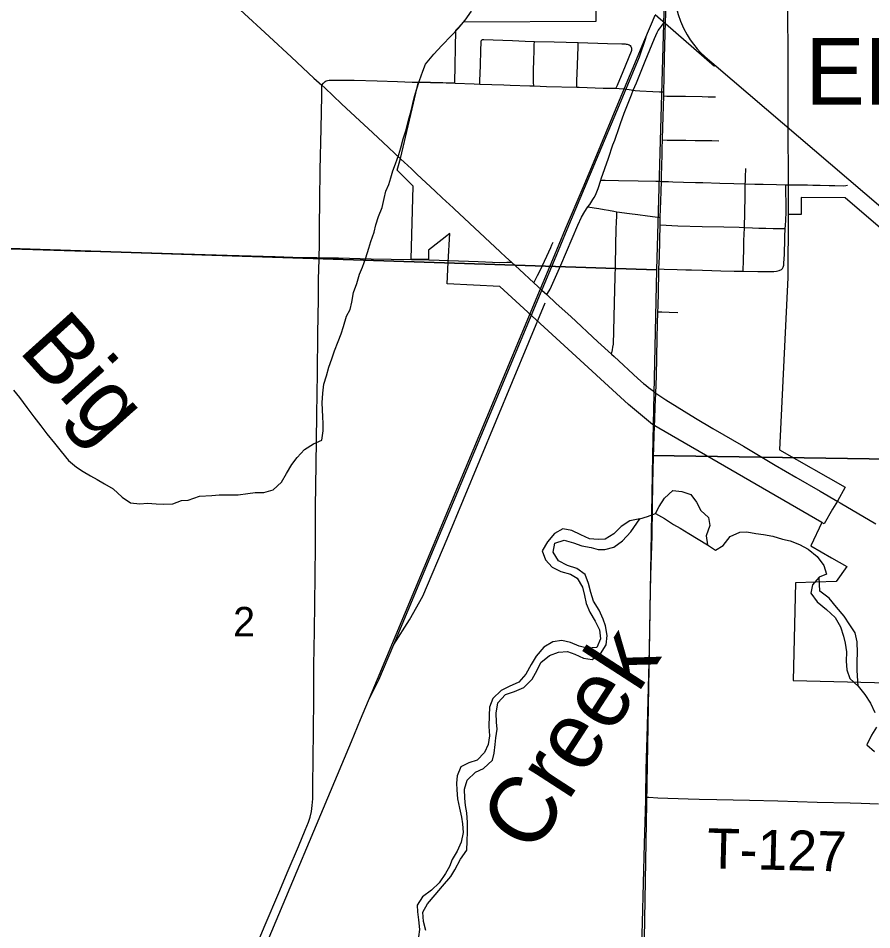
# Model space of a CAD drawing. Extents: x 0 to 34, y 0 to 22.
# Drawn here: x 7.066 to 8.28, y 14.663 to 15.96 of the extents above; entities that cross this region are included whole.
import ezdxf

# ---------------------------------------------------------------- set-up
doc = ezdxf.new("R2010")
doc.units = 0
for name, color, linetype in [('Default', 7, 'Continuous'), ('GM_X_City_Street', 7, 'Continuous'), ('GM_X_Corporation', 7, 'Continuous'), ('GM_X_County_Road', 7, 'Continuous'), ('GM_X_County_Road_Text', 7, 'Continuous'), ('GM_X_Interchange_Ramps', 7, 'Continuous'), ('GM_X_Major_River_Text', 7, 'Continuous'), ('GM_X_Minor_River', 7, 'Continuous'), ('GM_X_Section', 7, 'Continuous'), ('GM_X_Section_Text', 7, 'Continuous'), ('GM_X_State_Shield', 7, 'Continuous'), ('GM_X_Unincorporated', 7, 'Continuous'), ('GM_X_Unincorporated_Location', 7, 'Continuous'), ('GM_X_US_Location', 7, 'Continuous'), ('GM_X_US_Shield', 7, 'Continuous')]:
    doc.layers.add(name, color=color, linetype=linetype)

msp = doc.modelspace()

# ---------------------------------------------------------------- linework, layer by layer
at = {"layer": 'Default'}
for points in [[(8.8, 15.3246), (8.8, 16.334), (7.9948, 16.3527), (7.9737, 15.6015), (7.9679, 15.3374)], [(8.8, 14.3281), (8.8, 15.3246), (7.9679, 15.3374), (7.9551, 14.5952), (7.9448, 14.3373)]]:
    msp.add_lwpolyline(points, close=True, dxfattribs=at)
msp.add_lwpolyline([(8.385, 15.5812), (8.2421, 15.7041), (8.1796, 15.7048), (8.1793, 15.6802), (8.1608, 15.6804), (8.1604, 15.591), (8.1484, 15.3458), (8.2418, 15.2923), (8.2312, 15.2728), (8.2242, 15.2612), (8.2123, 15.2402), (8.2087, 15.2423), (8.1932, 15.209), (8.2227, 15.1919), (8.2443, 15.1795), (8.2293, 15.1583), (8.1715, 15.1566), (8.1681, 15.0172), (8.4377, 15.0106)], dxfattribs=at)
at = {"layer": 'GM_X_City_Street'}
for p, q in [((7.9839, 15.8491), (7.984, 15.8548)), ((7.9788, 15.6656), (7.9791, 15.676)), ((7.6251, 15.6163), (7.6499, 15.6157))]:
    msp.add_line(p, q, dxfattribs=at)
for points in [[(7.9867, 15.9546), (7.9871, 15.9656), (7.9887, 16.009), (7.989, 16.0249)], [(7.984, 15.8548), (7.9845, 15.8758), (7.9852, 15.9036), (7.9861, 15.9377), (7.9867, 15.9546)], [(7.9822, 15.7866), (7.9828, 15.8046), (7.9839, 15.8491)], [(7.9807, 15.7276), (7.981, 15.7391), (7.9811, 15.7457), (7.9814, 15.7534), (7.9816, 15.7618), (7.9819, 15.7745), (7.9822, 15.7866)], [(7.9791, 15.676), (7.9795, 15.6885), (7.9798, 15.6992), (7.9802, 15.7135), (7.9807, 15.7276)], [(7.9772, 15.6029), (7.9778, 15.6206), (7.9788, 15.6656)], [(6.9928, 15.6334), (7.0402, 15.6319), (7.0868, 15.6305), (7.1613, 15.6285), (7.2265, 15.6267), (7.2855, 15.625), (7.3632, 15.6225), (7.4315, 15.6206), (7.4563, 15.6198), (7.4905, 15.6191), (7.4938, 15.619)], [(7.4938, 15.619), (7.5215, 15.6186), (7.5681, 15.6174), (7.5961, 15.6171), (7.6251, 15.6163)], [(7.6499, 15.6157), (7.6645, 15.6153), (7.6784, 15.6149)], [(7.6784, 15.6149), (7.7201, 15.6135), (7.7511, 15.6123), (7.7608, 15.6124), (7.7675, 15.6124)], [(7.9757, 15.5421), (7.9759, 15.5494), (7.9764, 15.5698), (7.9767, 15.58), (7.9769, 15.589), (7.9772, 15.6029)], [(7.9727, 15.4263), (7.9735, 15.4504), (7.9748, 15.5046), (7.9753, 15.5244), (7.9757, 15.5421)], [(7.9709, 15.3803), (7.9712, 15.3885), (7.9719, 15.4071), (7.9727, 15.4256), (7.9727, 15.4263)], [(7.9584, 14.8515), (7.9592, 14.8907), (7.9611, 14.9529), (7.9614, 14.9715), (7.9631, 15.043), (7.964, 15.0834), (7.9648, 15.1207), (7.9658, 15.1673), (7.9674, 15.2232), (7.9681, 15.2636), (7.9685, 15.2978), (7.9696, 15.3351), (7.9709, 15.3803)], [(7.9516, 14.5947), (7.952, 14.6079), (7.9537, 14.6731), (7.9564, 14.785), (7.9583, 14.8472), (7.9584, 14.8515)]]:
    msp.add_lwpolyline(points, dxfattribs=at)
at = {"layer": 'GM_X_Corporation'}
msp.add_line((7.9718, 15.9648), (8.0563, 15.8914), dxfattribs=at)
for points in [[(8.0101, 16.0566), (8.0064, 16.0438), (8.0032, 16.0324), (8.0011, 16.0214), (8, 16.0122), (7.9995, 15.9972), (8, 15.9869), (8.0018, 15.9759), (8.0044, 15.965), (8.008, 15.9554), (8.0122, 15.9455), (8.0171, 15.9362), (8.0217, 15.929), (8.0261, 15.9226), (8.0314, 15.9163), (8.0364, 15.9108), (8.0427, 15.9049), (8.0587, 15.8914), (8.5043, 15.5105), (8.8, 15.2581)], [(7.1503, 14), (7.403, 14.6041), (7.5398, 14.9308), (7.5529, 14.9621), (7.5767, 15.0193), (7.6567, 15.2102), (7.6827, 15.2726), (7.7324, 15.3914), (7.8087, 15.5745), (7.8264, 15.6162), (7.8444, 15.66), (7.8693, 15.7188), (7.8863, 15.7598), (7.9189, 15.8374), (7.9573, 15.9292), (7.972, 15.9642)], [(7.6, 15.0687), (7.6589, 15.2093), (7.6849, 15.2717), (7.7346, 15.3905), (7.8109, 15.5736), (7.8286, 15.6153), (7.8466, 15.6591), (7.8715, 15.7179), (7.8885, 15.7589), (7.9211, 15.8365), (7.9496, 15.9048), (7.9588, 15.9329)], [(7.6, 15.0687), (7.6223, 15.1039), (7.6414, 15.1375), (7.6758, 15.2191), (7.8155, 15.5548)], [(7.5633, 14.9872), (7.5789, 15.0184), (7.6, 15.0687)]]:
    msp.add_lwpolyline(points, dxfattribs=at)
at = {"layer": 'GM_X_County_Road'}
for points in [[(7.0027, 16.3195), (7.0291, 16.2956), (7.0799, 16.2498), (7.1558, 16.1809), (7.1925, 16.1473), (7.2336, 16.1094), (7.2657, 16.08), (7.3452, 16.0057), (7.3814, 15.9718), (7.4226, 15.9339), (7.4544, 15.9041), (7.4861, 15.8744), (7.4979, 15.8643), (7.5018, 15.8606), (7.5256, 15.8381), (7.5518, 15.8138)], [(7.5518, 15.8138), (7.5634, 15.803), (7.5845, 15.7833), (7.6096, 15.7598)], [(7.6096, 15.7598), (7.6154, 15.7544), (7.6194, 15.7507), (7.6255, 15.745), (7.6316, 15.7394), (7.633, 15.738)], [(7.633, 15.738), (7.6588, 15.7137), (7.669, 15.7043)], [(7.669, 15.7043), (7.6846, 15.6899), (7.686, 15.6886)], [(7.686, 15.6886), (7.7514, 15.6273), (7.7595, 15.6198)], [(7.7595, 15.6198), (7.7675, 15.6124), (7.7787, 15.6021), (7.7992, 15.5832), (7.8107, 15.5728), (7.8177, 15.5664), (7.8311, 15.5539), (7.8517, 15.5351), (7.8904, 15.4994), (7.9099, 15.4817), (7.9133, 15.4786), (7.9473, 15.4471), (7.9554, 15.4401), (7.9585, 15.4374), (7.9621, 15.4345), (7.9687, 15.4294), (7.9727, 15.4263), (7.9871, 15.4167), (8.0293, 15.3908), (8.054, 15.376), (8.0972, 15.3507), (8.1423, 15.324), (8.1717, 15.3068), (8.2064, 15.2867), (8.2315, 15.2723)], [(8.2315, 15.2723), (8.2349, 15.2701), (8.2857, 15.2401)]]:
    msp.add_lwpolyline(points, dxfattribs=at)
at = {"layer": 'GM_X_Interchange_Ramps'}
for points in [[(7.4938, 15.619), (7.4942, 15.6382), (7.4944, 15.6631), (7.4948, 15.7004), (7.4953, 15.7439), (7.4967, 15.8029), (7.4975, 15.8495), (7.4979, 15.8643)], [(7.4979, 15.8643), (7.5002, 15.8673), (7.5025, 15.8695), (7.5041, 15.8706), (7.5058, 15.8713), (7.5081, 15.8716), (7.511, 15.8718), (7.5174, 15.8718), (7.5436, 15.8714), (7.5766, 15.8704), (7.6053, 15.8695), (7.626, 15.8689), (7.6354, 15.8685), (7.6364, 15.8685)], [(7.6364, 15.8685), (7.6524, 15.8681), (7.6746, 15.8676), (7.6872, 15.8673)], [(7.6872, 15.8673), (7.7145, 15.8663), (7.7225, 15.866)], [(8.1575, 15.7228), (8.1624, 15.7228), (8.1677, 15.7227), (8.1752, 15.7227), (8.1806, 15.7227)], [(8.1806, 15.7227), (8.1884, 15.7225), (8.1959, 15.7224), (8.2066, 15.7221), (8.2191, 15.7218), (8.2273, 15.7216), (8.2393, 15.7214), (8.2428, 15.7215), (8.2455, 15.7222)], [(7.4039, 14.6382), (7.4173, 14.6697), (7.4366, 14.7155), (7.4498, 14.747), (7.4643, 14.7813), (7.4739, 14.8043), (7.4786, 14.8158), (7.4813, 14.823), (7.4831, 14.8309), (7.4842, 14.8396), (7.4849, 14.8491), (7.4851, 14.8677), (7.4858, 14.9453), (7.4862, 14.9919), (7.4864, 15.0386), (7.4873, 15.0883), (7.4881, 15.166), (7.4886, 15.2095), (7.4889, 15.2654), (7.489, 15.2934), (7.4899, 15.3586), (7.4905, 15.3959), (7.4915, 15.4549), (7.4922, 15.5108), (7.4929, 15.5605), (7.4932, 15.5885), (7.4937, 15.6165), (7.4938, 15.619)], [(7.9584, 14.8515), (7.963, 14.8512), (7.9754, 14.8506), (8.0189, 14.8492), (8.0345, 14.8488), (8.0594, 14.8482), (8.106, 14.8472), (8.1464, 14.846), (8.2024, 14.8444), (8.2491, 14.8432), (8.2646, 14.8428), (8.2895, 14.8421)]]:
    msp.add_lwpolyline(points, dxfattribs=at)
at = {"layer": 'GM_X_Section'}
for points in [[(7.3235, 15.2796), (7.3412, 15.2806), (7.3519, 15.2817), (7.3789, 15.2817), (7.3926, 15.2836), (7.4028, 15.2847), (7.415, 15.2847), (7.4287, 15.2885), (7.4405, 15.2995), (7.4473, 15.3117), (7.455, 15.3246), (7.4626, 15.3349), (7.4732, 15.3463), (7.4858, 15.3542), (7.4976, 15.3595), (7.4995, 15.3728), (7.4995, 15.3831), (7.4991, 15.3926), (7.4987, 15.4025), (7.4984, 15.4127), (7.4991, 15.426), (7.5007, 15.4389), (7.5045, 15.4511), (7.5075, 15.4633), (7.5121, 15.475), (7.5159, 15.4864), (7.5208, 15.4997), (7.525, 15.5107), (7.5285, 15.521), (7.533, 15.5358), (7.538, 15.5453), (7.5406, 15.5556), (7.5429, 15.5693), (7.5475, 15.5822), (7.5513, 15.5955), (7.5555, 15.6057), (7.5605, 15.6186), (7.5646, 15.6323), (7.5673, 15.6422), (7.5723, 15.6555), (7.5745, 15.6657), (7.5784, 15.6775), (7.5833, 15.6904), (7.5864, 15.7034), (7.5886, 15.7136), (7.5928, 15.7231), (7.5959, 15.7326), (7.5989, 15.7425), (7.6024, 15.7524), (7.6073, 15.766), (7.61, 15.7755), (7.6134, 15.7881), (7.6176, 15.801), (7.621, 15.8147), (7.6248, 15.828), (7.6271, 15.8386), (7.6294, 15.8485), (7.6324, 15.858), (7.6366, 15.8709), (7.6412, 15.8842), (7.645, 15.8945), (7.6572, 15.9085), (7.6686, 15.921), (7.6823, 15.9351), (7.6914, 15.945), (7.7017, 15.9571), (7.7108, 15.9697)], [(7.0594, 15.4307), (7.0678, 15.4201), (7.0781, 15.4057), (7.088, 15.3925), (7.0983, 15.3796), (7.1067, 15.3686), (7.1174, 15.355), (7.1269, 15.3433), (7.1375, 15.3304), (7.1486, 15.321), (7.1581, 15.3146), (7.1687, 15.3085), (7.1782, 15.3036), (7.1885, 15.2972), (7.201, 15.2901), (7.2136, 15.2784), (7.2254, 15.27), (7.2387, 15.2686), (7.25, 15.2697), (7.2622, 15.269), (7.272, 15.2683), (7.2857, 15.2687), (7.2982, 15.2733), (7.3077, 15.2741), (7.3235, 15.2796)], [(7.9723, 15.2549), (7.9852, 15.2477), (7.9977, 15.2393), (8.0072, 15.234), (8.0198, 15.2268), (8.0464, 15.2104)]]:
    msp.add_lwpolyline(points, dxfattribs=at)
at = {"layer": 'GM_X_Section_Text'}
for points in [[(7.9498, 15.2473), (7.9608, 15.2507), (7.9723, 15.2549), (7.9776, 15.2651), (7.9852, 15.2769), (7.997, 15.2876), (8.0099, 15.2864), (8.0225, 15.2819), (8.0305, 15.2712), (8.0365, 15.2594), (8.0476, 15.2495), (8.0495, 15.2378), (8.0445, 15.2233), (8.0464, 15.2104), (8.0574, 15.2028), (8.0685, 15.2096), (8.0784, 15.2222), (8.0921, 15.2283), (8.102, 15.229), (8.1149, 15.2267), (8.1259, 15.2252), (8.1389, 15.2229), (8.1529, 15.2187), (8.1636, 15.2161), (8.1769, 15.2111), (8.1894, 15.2043), (8.202, 15.194), (8.2115, 15.1811), (8.2153, 15.1689), (8.205, 15.1644)], [(7.9498, 15.2473), (7.9357, 15.2446), (7.9236, 15.2367), (7.9129, 15.226), (7.9007, 15.2184), (7.8905, 15.2181), (7.8783, 15.2188), (7.8661, 15.2245), (7.8532, 15.2306), (7.8403, 15.2333), (7.8285, 15.2264), (7.8186, 15.2147), (7.8113, 15.2021), (7.8159, 15.1892), (7.8254, 15.1786), (7.8376, 15.1725), (7.8513, 15.1687), (7.8608, 15.163), (7.8684, 15.1501), (7.8714, 15.1383), (7.8737, 15.1269), (7.879, 15.1147), (7.8866, 15.1018), (7.8927, 15.0897), (7.8942, 15.0767), (7.8889, 15.0646), (7.8752, 15.0634), (7.8638, 15.0665), (7.8516, 15.0714), (7.839, 15.0741), (7.8261, 15.0726), (7.8136, 15.065), (7.8025, 15.0521), (7.7953, 15.0403), (7.7877, 15.0262), (7.7778, 15.0152), (7.7641, 15.0088), (7.7527, 15.0031), (7.7409, 14.9917), (7.7363, 14.9795), (7.7355, 14.9674), (7.7351, 14.9518), (7.7363, 14.9389), (7.7344, 14.9263), (7.729, 14.915), (7.7184, 14.9039), (7.7066, 14.9005), (7.6952, 14.8944), (7.6902, 14.8819), (7.6891, 14.8713), (7.6898, 14.8618), (7.6906, 14.8492), (7.6936, 14.8356), (7.6963, 14.823), (7.6978, 14.8135), (7.6986, 14.801), (7.6959, 14.7873), (7.6902, 14.7748), (7.6833, 14.7626), (7.6791, 14.7527), (7.6738, 14.7429), (7.6647, 14.7296), (7.6536, 14.7193), (7.6411, 14.7094), (7.6331, 14.6977), (7.6338, 14.6882), (7.635, 14.6768), (7.6365, 14.6631), (7.6353, 14.6528)], [(7.6456, 14.6616), (7.6422, 14.6745), (7.6414, 14.6878), (7.6479, 14.6996), (7.6589, 14.7125), (7.6692, 14.7246), (7.681, 14.7387), (7.6871, 14.7482), (7.6951, 14.7634), (7.7039, 14.7759), (7.7043, 14.7888), (7.705, 14.8021), (7.705, 14.8154), (7.7039, 14.8291), (7.702, 14.8397), (7.7009, 14.85), (7.7005, 14.8629), (7.7043, 14.8754), (7.7161, 14.8868), (7.7275, 14.8922), (7.7404, 14.9043), (7.7427, 14.9138), (7.7443, 14.9263), (7.7454, 14.9358), (7.7469, 14.9484), (7.7462, 14.9583), (7.7458, 14.9708), (7.7481, 14.9856), (7.7587, 14.9974), (7.7717, 15.0016), (7.785, 15.0073), (7.7968, 15.0194), (7.804, 15.0319), (7.809, 15.043), (7.8215, 15.0528), (7.8341, 15.0578), (7.847, 15.0585), (7.8573, 15.0551), (7.8698, 15.049), (7.8824, 15.0475), (7.8942, 15.0555), (7.9022, 15.068), (7.9033, 15.0813), (7.9011, 15.095), (7.898, 15.1045), (7.8919, 15.1174), (7.8843, 15.1303), (7.8802, 15.1428), (7.8771, 15.1554), (7.8722, 15.1683), (7.8604, 15.177), (7.8471, 15.1812), (7.8341, 15.1877), (7.8265, 15.1999), (7.8292, 15.2128), (7.8422, 15.2173), (7.8558, 15.2135), (7.8676, 15.209), (7.8806, 15.2067), (7.8905, 15.2036), (7.9003, 15.2036), (7.9129, 15.207), (7.9255, 15.2162), (7.9373, 15.2287), (7.9498, 15.2473)], [(8.205, 15.1644), (8.1955, 15.1534), (8.1932, 15.1416), (8.202, 15.1294), (8.2156, 15.1184), (8.2278, 15.107), (8.2354, 15.0937), (8.2396, 15.0804), (8.2419, 15.0705), (8.2438, 15.0584), (8.2434, 15.0451), (8.2445, 15.0325), (8.2487, 15.0204), (8.2605, 15.0094)], [(8.2605, 15.0094), (8.259, 15.0318), (8.259, 15.0447), (8.2597, 15.0568), (8.259, 15.0724), (8.2563, 15.085), (8.2484, 15.0967), (8.2407, 15.1089), (8.2297, 15.1218), (8.2191, 15.1347), (8.2061, 15.1443), (8.205, 15.1644)], [(8.2605, 15.0094), (8.27, 14.9976), (8.278, 14.985), (8.284, 14.9717)], [(8.2867, 14.9508), (8.2795, 14.9394), (8.273, 14.9258), (8.2836, 14.9163)]]:
    msp.add_lwpolyline(points, dxfattribs=at)
at = {"layer": 'GM_X_Unincorporated_Location'}
for points in [[(8.0033, 16.6164), (7.9948, 16.3527), (7.9737, 15.6015), (6.9963, 15.6339), (7.0019, 16.6421)], [(6.9963, 15.6339), (7.9737, 15.6015), (7.9679, 15.3374), (7.9551, 14.5952), (6.9808, 14.6254)]]:
    msp.add_lwpolyline(points, close=True, dxfattribs=at)
at = {"layer": 'GM_X_US_Location'}
for points in [[(7.8177, 15.5664), (7.8208, 15.5718), (7.8223, 15.5744), (7.8264, 15.5828), (7.8378, 15.6082), (7.862, 15.6653), (7.8672, 15.6765), (7.8716, 15.6847), (7.875, 15.6899), (7.8762, 15.6915), (7.8788, 15.6948), (7.8831, 15.7016), (7.8849, 15.7046), (7.8868, 15.7078), (7.8889, 15.7126), (7.8905, 15.7172), (7.8945, 15.7294), (7.895, 15.7312), (7.9052, 15.7605), (7.9118, 15.7794), (7.9142, 15.7862), (7.9204, 15.8042), (7.9224, 15.81), (7.9276, 15.8248), (7.938, 15.8507), (7.9407, 15.8573), (7.9451, 15.8679), (7.9577, 15.8986), (7.9709, 15.931), (7.9746, 15.9395), (7.9761, 15.9422), (7.9778, 15.9448), (7.9808, 15.9486), (7.9832, 15.9515), (7.9867, 15.9546)], [(7.7225, 15.866), (7.7226, 15.8707), (7.7232, 15.8926), (7.7238, 15.9141), (7.7241, 15.925), (7.7241, 15.9258), (7.7242, 15.9266), (7.7244, 15.9272), (7.7246, 15.9279), (7.725, 15.9284)], [(7.725, 15.9284), (7.7258, 15.9291), (7.7264, 15.9292), (7.7271, 15.9293), (7.7281, 15.9294), (7.7416, 15.929), (7.7688, 15.9279), (7.7869, 15.9272), (7.8, 15.9267), (7.8283, 15.9259), (7.8625, 15.925), (7.9041, 15.9238), (7.9242, 15.9233), (7.9289, 15.9232), (7.9306, 15.923), (7.9321, 15.9228), (7.9333, 15.9225), (7.9346, 15.9219), (7.936, 15.9209), (7.937, 15.9197), (7.9378, 15.9184), (7.9381, 15.9169), (7.9381, 15.9153), (7.938, 15.9139), (7.9376, 15.9123), (7.926, 15.8836), (7.9176, 15.8641), (7.9158, 15.86)], [(7.799, 15.8634), (7.7989, 15.8682), (7.7988, 15.8781), (7.7989, 15.8876), (7.7991, 15.8976), (7.7997, 15.9159), (7.7999, 15.922), (7.8, 15.9267)], [(7.8604, 15.8615), (7.8604, 15.8662), (7.8605, 15.8715), (7.8608, 15.8807), (7.8622, 15.9192), (7.8625, 15.925)], [(7.7225, 15.866), (7.7564, 15.8649), (7.7655, 15.8646), (7.7934, 15.8636), (7.799, 15.8634), (7.8174, 15.8627), (7.8604, 15.8615), (7.8637, 15.8614), (7.8979, 15.8604), (7.9102, 15.8601), (7.9158, 15.86), (7.9206, 15.8599), (7.9284, 15.859), (7.935, 15.8581), (7.9407, 15.8573), (7.9432, 15.8569), (7.9501, 15.8562), (7.9686, 15.8556), (7.978, 15.8551), (7.984, 15.8548)], [(7.9839, 15.8491), (7.9884, 15.849), (8.0151, 15.8486), (8.0386, 15.8482), (8.0473, 15.848), (8.0577, 15.8479)], [(7.9822, 15.7866), (7.989, 15.7864), (8.0021, 15.7862), (8.0152, 15.786), (8.0289, 15.7858), (8.0409, 15.7856), (8.0525, 15.7855), (8.0623, 15.7853)], [(8.0969, 15.5997), (8.0971, 15.6049), (8.0972, 15.6109), (8.0975, 15.6192), (8.0977, 15.6275), (8.0979, 15.6366), (8.0981, 15.6438), (8.0983, 15.6515), (8.0986, 15.662), (8.0986, 15.6628), (8.0992, 15.6823), (8.0994, 15.6906), (8.0997, 15.6993), (8.0998, 15.7091), (8.1, 15.7197), (8.1, 15.724), (8.1001, 15.7275), (8.1003, 15.7336), (8.1006, 15.7459)], [(7.8945, 15.7294), (7.9005, 15.7293), (7.9194, 15.7288), (7.9477, 15.7285), (7.9725, 15.7278), (7.9772, 15.7277), (7.9807, 15.7276)], [(7.9807, 15.7276), (7.9909, 15.7273), (7.9971, 15.727), (8.0123, 15.7266), (8.0292, 15.7261), (8.0394, 15.7258), (8.0637, 15.7251), (8.0835, 15.7245), (8.1, 15.724), (8.1137, 15.7237), (8.1252, 15.7235), (8.1445, 15.7231), (8.1575, 15.7228)], [(8.158, 15.6803), (8.1581, 15.6883), (8.158, 15.6969), (8.1578, 15.712), (8.1575, 15.7228)], [(7.8762, 15.6915), (7.8848, 15.69), (7.8917, 15.6888), (7.8991, 15.6875), (7.9055, 15.6864), (7.913, 15.6851), (7.9173, 15.6844)], [(7.9099, 15.4817), (7.9111, 15.4881), (7.9117, 15.4915), (7.9123, 15.4959), (7.913, 15.5145), (7.914, 15.5548), (7.915, 15.5918), (7.9152, 15.6068), (7.9159, 15.6377), (7.9165, 15.6593), (7.9169, 15.6704), (7.9171, 15.6778), (7.9173, 15.6844)], [(7.9173, 15.6844), (7.9353, 15.6819), (7.9471, 15.6803), (7.9611, 15.6785), (7.9719, 15.677), (7.9791, 15.676)], [(8.1514, 15.6021), (8.1529, 15.6036), (8.154, 15.6056), (8.1548, 15.6083), (8.1549, 15.6114), (8.1555, 15.6237), (8.1562, 15.6458), (8.1564, 15.6526), (8.1565, 15.6569), (8.1567, 15.6603), (8.1572, 15.6647), (8.1576, 15.6722), (8.1578, 15.6756), (8.158, 15.6803)], [(7.9788, 15.6656), (8.0041, 15.6645), (8.0384, 15.6634), (8.0696, 15.6628), (8.0914, 15.6622), (8.0986, 15.662), (8.1104, 15.6615), (8.1194, 15.6612), (8.1292, 15.6609), (8.1394, 15.6607), (8.147, 15.6605), (8.1548, 15.6604), (8.1567, 15.6603)], [(7.7992, 15.5832), (7.8011, 15.5868), (7.8046, 15.5935), (7.8089, 15.6019), (7.8233, 15.6333), (7.8249, 15.6371), (7.8266, 15.6412)], [(7.9772, 15.6029), (7.9844, 15.6026), (8.0031, 15.602), (8.0154, 15.6017), (8.0234, 15.6015), (8.039, 15.6011), (8.0524, 15.6007), (8.0654, 15.6004), (8.0839, 15.5999), (8.0969, 15.5997), (8.118, 15.5994), (8.1367, 15.5992), (8.1405, 15.5994), (8.1443, 15.5997), (8.1483, 15.6007), (8.1514, 15.6021)], [(7.9757, 15.5421), (7.9811, 15.5419), (7.9916, 15.5416), (8.0038, 15.5408)]]:
    msp.add_lwpolyline(points, dxfattribs=at)
at = {"layer": 'GM_X_US_Shield'}
msp.add_lwpolyline([(8.1598, 16.0244), (8.1608, 15.6804), (8.1604, 15.591), (8.1484, 15.3458), (8.2418, 15.2923), (8.2312, 15.2728), (8.2242, 15.2612), (8.2123, 15.2402), (8.2087, 15.2423), (7.9682, 15.3815), (7.9337, 15.41), (7.7509, 15.5781), (7.676, 15.5816), (7.6773, 15.6124), (7.6797, 15.6534), (7.6495, 15.6297), (7.6496, 15.6162), (7.6249, 15.6169), (7.6278, 15.7209), (7.6047, 15.7435), (7.6094, 15.7603), (7.6352, 15.869), (7.6869, 15.8679), (7.6885, 15.9428), (7.6997, 15.9544), (7.8881, 15.9555), (7.8888, 16.0258)], dxfattribs=at)

# ---------------------------------------------------------------- texts
at = {"layer": 'GM_X_County_Road_Text'}
msp.add_text('T-127', height=0.05682, rotation=358.5956, dxfattribs=at).set_placement((8.0451, 14.7504))
at = {"layer": 'GM_X_Major_River_Text'}
msp.add_text('2', height=0.0419, rotation=0, dxfattribs=at).set_placement((7.3716, 15.0802))
at = {"layer": 'GM_X_Minor_River'}
msp.add_text('Big', height=0.09472, rotation=312.0759, dxfattribs=at).set_placement((7.0648, 15.4865))
at = {"layer": 'GM_X_State_Shield'}
msp.add_text('Creek', height=0.09471, rotation=57.0781, dxfattribs=at).set_placement((7.7979, 14.7676))
at = {"layer": 'GM_X_Unincorporated'}
msp.add_text('EDISON', height=0.0947, rotation=0, dxfattribs=at).set_placement((8.1854, 15.8368))

doc.saveas('drawing.dxf')
